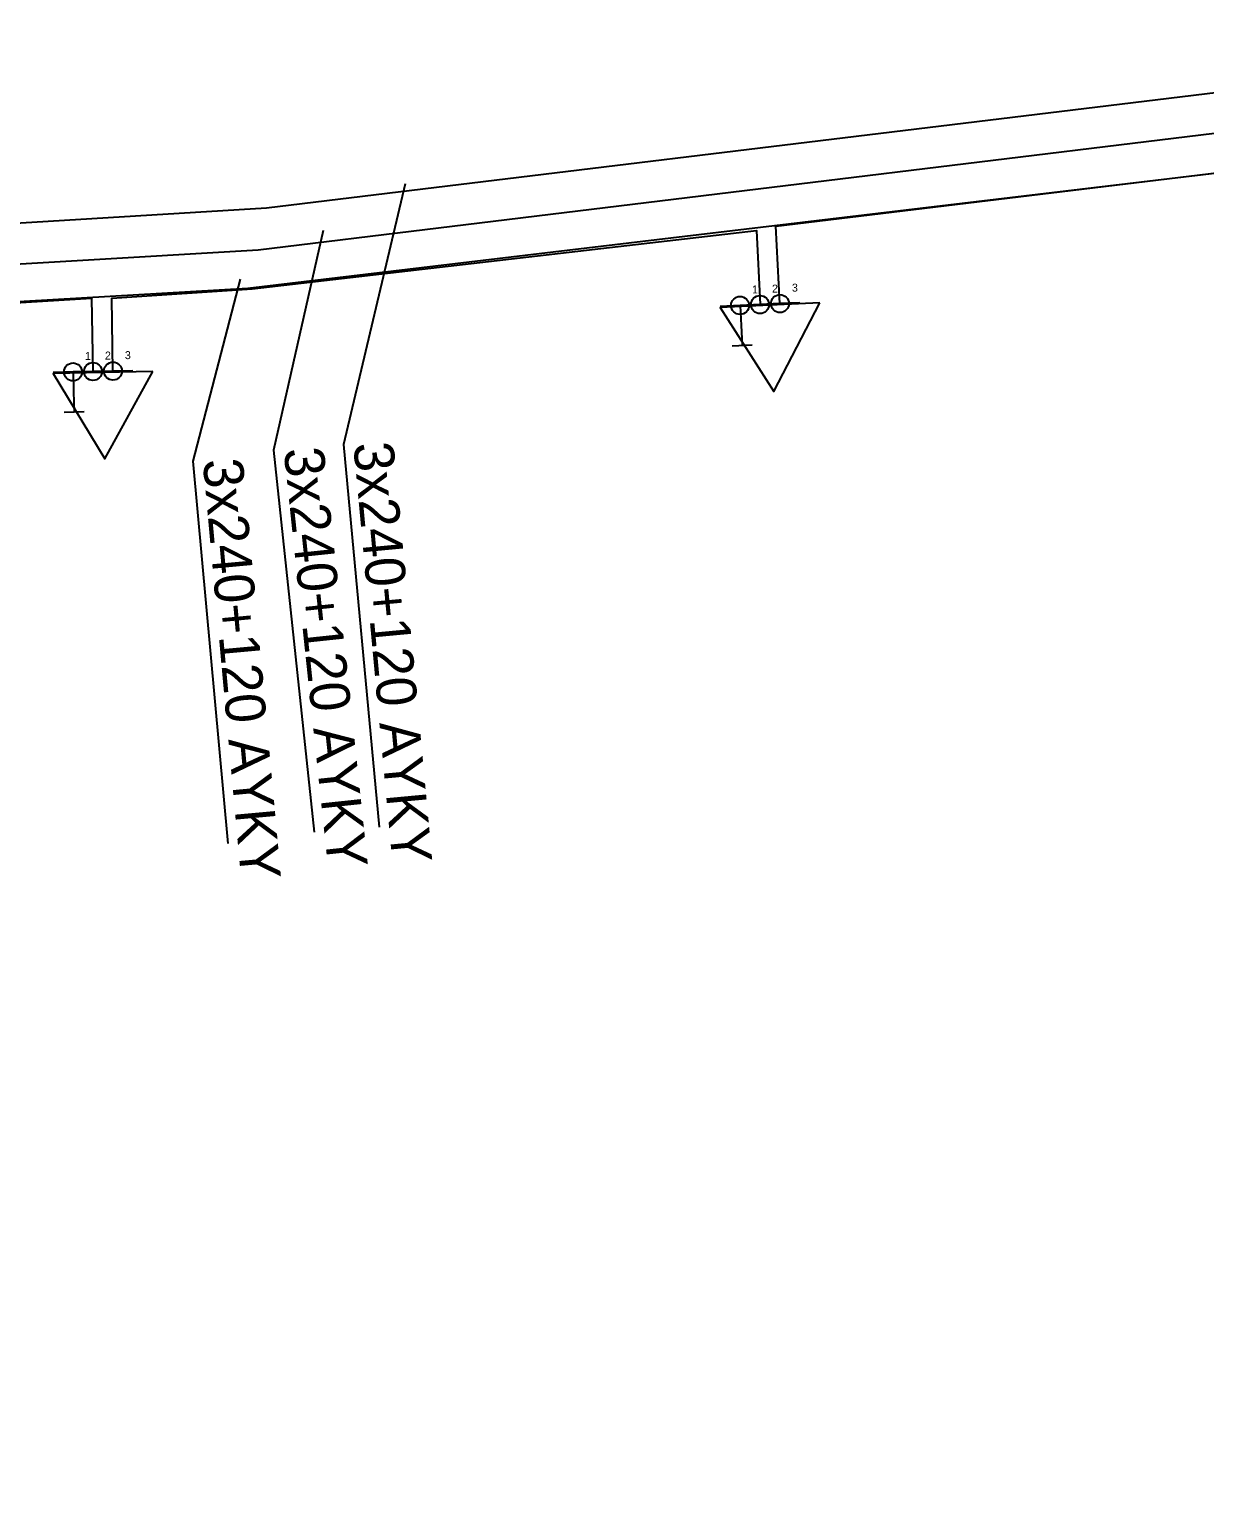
# Model space of a CAD drawing. Extents: x -744800 to -744528, y -1052473 to -1052336.
# Drawn here: x -744674.38 to -744644.94, y -1052436.29 to -1052399.19 of the extents above; entities that cross this region are included whole.
import ezdxf

# ---------------------------------------------------------------- set-up
doc = ezdxf.new("R2010")
doc.units = 0
for name, color, linetype in [('NN_CISLO_VYVODU_SP', 7, 'Continuous'), ('NN_KABEL_INSTALACE_SP_PROVOZ', 7, 'Continuous'), ('NN_KABELOVE_VEDENI_PROVOZ', 7, 'Continuous'), ('NN_POPIS_USEKU', 7, 'Continuous'), ('NN_PRIPOJKOVA_SKRIN', 7, 'Continuous'), ('NN_PRIPOJNICE_SP', 7, 'Continuous'), ('NN_PRIPOJOVACI_MISTO', 7, 'Continuous'), ('NN_VYVODY_SP', 7, 'Continuous'), ('TRASA_KABELU_NN_PROVOZ', 7, 'Continuous')]:
    doc.layers.add(name, color=color, linetype=linetype)

msp = doc.modelspace()

# ---------------------------------------------------------------- linework, layer by layer
at = {"layer": 'NN_KABEL_INSTALACE_SP_PROVOZ'}
for p, q in [((-744656.572, -1052406.102), (-744656.549, -1052406.602)), ((-744673.288, -1052407.768), (-744673.277, -1052408.268))]:
    msp.add_line(p, q, dxfattribs=at)
at = {"layer": 'NN_KABELOVE_VEDENI_PROVOZ'}
for points in [[(-744799.958, -1052408.482), (-744800.116, -1052406.505), (-744794.132, -1052405.926), (-744768.563, -1052404.243), (-744751.319, -1052402.793), (-744733.275, -1052401.051), (-744733.48, -1052398.511), (-744731.401, -1052398.392), (-744727.771, -1052398.622), (-744714.274, -1052400.592), (-744713.445, -1052400.003), (-744705.181, -1052400.423), (-744705.583, -1052403.661), (-744687.509, -1052405.817), (-744668.651, -1052404.712), (-744627.976, -1052399.751), (-744625.876, -1052400.487), (-744566.945, -1052393.578), (-744568.26, -1052383.974), (-744549.76, -1052382.661), (-744547.856, -1052381.455), (-744527.683, -1052380.355), (-744528.085, -1052374.982), (-744530.485, -1052375.105)], [(-744701.233, -1052459.94), (-744697.975, -1052462.013), (-744701.204, -1052455.312), (-744721.631, -1052413.856), (-744727.534, -1052401.666), (-744727.626, -1052397.603), (-744714.621, -1052399.45), (-744713.238, -1052398.803), (-744704.151, -1052399.748), (-744704.544, -1052402.838), (-744687.321, -1052404.806), (-744668.44, -1052403.653), (-744628.032, -1052398.743), (-744625.696, -1052399.462), (-744568.109, -1052392.689), (-744569.387, -1052383.09), (-744550.152, -1052381.714), (-744547.961, -1052380.354), (-744528.632, -1052379.391), (-744528.92, -1052376.499)], [(-744655.573, -1052406.056), (-744655.676, -1052404.119), (-744638.425, -1052402.024), (-744638.199, -1052403.704)], [(-744705.655, -1052404.561), (-744687.56, -1052406.823), (-744672.821, -1052405.918), (-744672.788, -1052407.757)], [(-744672.288, -1052407.747), (-744672.313, -1052405.918), (-744668.799, -1052405.685), (-744656.163, -1052404.225), (-744656.073, -1052406.08)]]:
    msp.add_lwpolyline(points, dxfattribs=at)
at = {"layer": 'NN_POPIS_USEKU'}
for points in [[(-744664.961, -1052403.056), (-744666.514, -1052409.588), (-744665.62, -1052419.169)], [(-744667.018, -1052404.227), (-744668.26, -1052409.73), (-744667.244, -1052419.299)], [(-744669.096, -1052405.441), (-744670.287, -1052409.999), (-744669.409, -1052419.582)]]:
    msp.add_lwpolyline(points, dxfattribs=at)
at = {"layer": 'NN_PRIPOJKOVA_SKRIN'}
for points in [[(-744654.572, -1052406.039), (-744657.069, -1052406.152), (-744655.723, -1052408.259)], [(-744671.287, -1052407.754), (-744673.787, -1052407.806), (-744672.492, -1052409.945)]]:
    msp.add_lwpolyline(points, close=True, dxfattribs=at)
at = {"layer": 'NN_PRIPOJNICE_SP'}
for points in [[(-744655.074, -1052406.034), (-744655.573, -1052406.056), (-744656.073, -1052406.08), (-744656.572, -1052406.102), (-744657.072, -1052406.126)], [(-744671.788, -1052407.736), (-744672.288, -1052407.747), (-744672.788, -1052407.757), (-744673.288, -1052407.768), (-744673.788, -1052407.779)]]:
    msp.add_lwpolyline(points, dxfattribs=at)
at = {"layer": 'NN_PRIPOJOVACI_MISTO'}
for p, q in [((-744656.549, -1052406.602), (-744656.523, -1052407.101)), ((-744656.772, -1052407.114), (-744656.273, -1052407.088)), ((-744673.277, -1052408.268), (-744673.26, -1052408.768)), ((-744673.509, -1052408.776), (-744673.01, -1052408.759))]:
    msp.add_line(p, q, dxfattribs=at)
at = {"layer": 'NN_VYVODY_SP'}
for centre in [(-744656.572, -1052406.102), (-744656.073, -1052406.08), (-744655.573, -1052406.056), (-744672.288, -1052407.747), (-744673.288, -1052407.768), (-744672.788, -1052407.757)]:
    msp.add_circle(centre, 0.225, dxfattribs=at)
at = {"layer": 'TRASA_KABELU_NN_PROVOZ'}
msp.add_lwpolyline([(-744707.06, -1052404.212), (-744705.621, -1052404.634), (-744687.963, -1052406.758), (-744687.133, -1052406.691), (-744684.137, -1052406.542), (-744680.842, -1052406.363), (-744668.909, -1052405.665), (-744645.458, -1052402.883), (-744625.739, -1052400.545)], dxfattribs=at)

# ---------------------------------------------------------------- texts
at = {"layer": 'NN_CISLO_VYVODU_SP'}
for s, p in [('1', (-744656.272, -1052405.802)), ('2', (-744655.773, -1052405.78)), ('3', (-744655.273, -1052405.756)), ('1', (-744672.988, -1052407.468)), ('2', (-744672.488, -1052407.457)), ('3', (-744671.988, -1052407.447))]:
    msp.add_text(s, height=0.2, dxfattribs=at).set_placement(p)
at = {"layer": 'NN_POPIS_USEKU'}
for rotation, p in [(276.0604, (-744668.011, -1052409.704)), (275.3341, (-744666.265, -1052409.564)), (275.2345, (-744670.038, -1052409.976))]:
    msp.add_text('3x240+120 AYKY', height=1, rotation=rotation, dxfattribs=at).set_placement(p)

doc.saveas('drawing.dxf')
